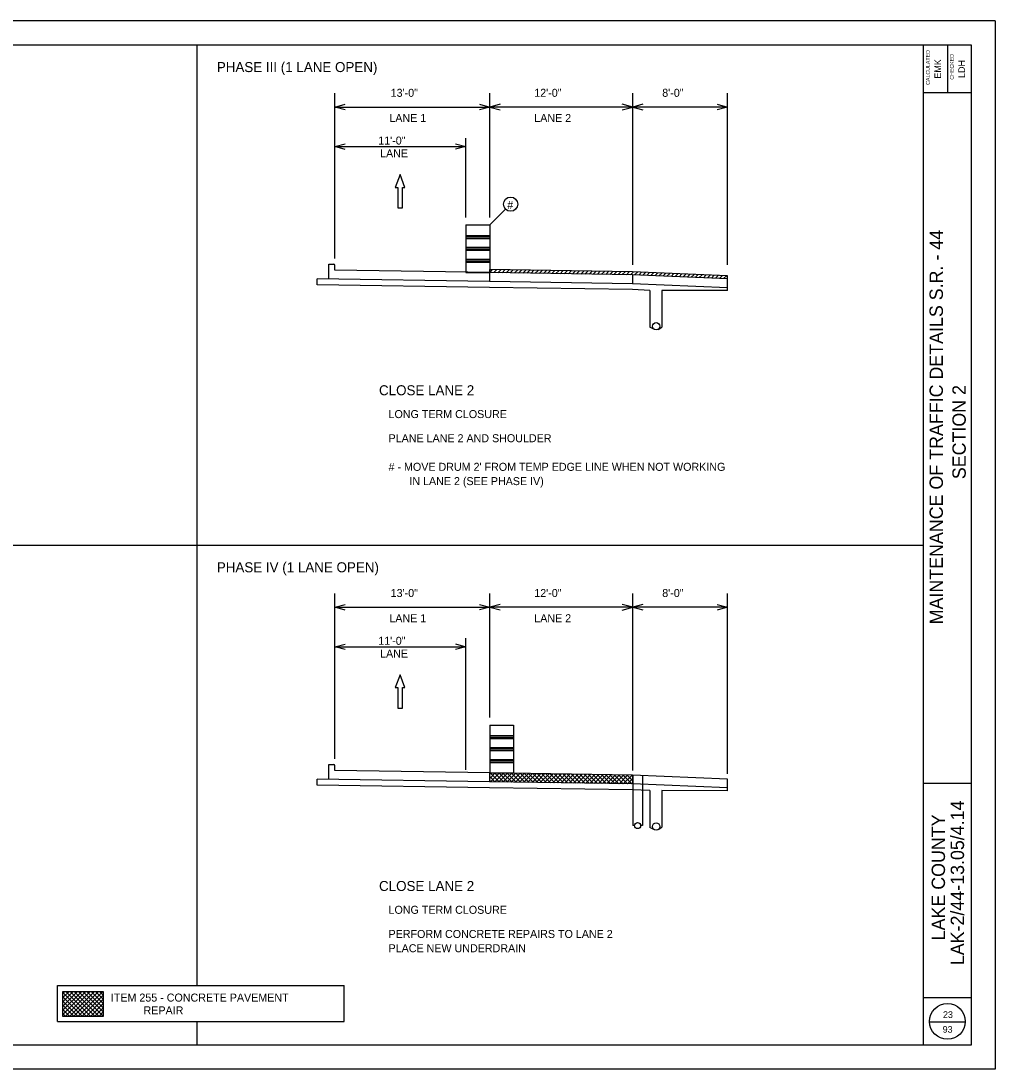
# Model space of a CAD drawing. Extents: x -161 to 291, y -369 to 173.
# Drawn here: x 117.8 to 199.6, y -270.5 to -182.5 of the extents above; entities that cross this region are included whole.
import ezdxf

# ---------------------------------------------------------------- set-up
doc = ezdxf.new("R2010")
doc.units = 0
for name, color, linetype in [('Level 1', 7, 'Continuous'), ('Level 11', 7, 'Continuous'), ('Level 21', 7, 'Continuous'), ('Level 25', 7, 'Continuous'), ('Level 26', 7, 'Continuous'), ('Level 6', 7, 'Continuous'), ('Level 7', 7, 'Continuous')]:
    doc.layers.add(name, color=color, linetype=linetype)

msp = doc.modelspace()

# ---------------------------------------------------------------- linework, layer by layer
at = {"layer": 'Level 1'}
for p, q in [((199.609, -182.503), (63.623, -182.503)), ((199.609, -182.503), (199.609, -270.494)), ((71.623, -184.503), (132.616, -184.503)), ((132.616, -226.499), (132.616, -184.503)), ((132.616, -184.503), (197.61, -184.503)), ((193.61, -201.501), (193.61, -184.503)), ((195.61, -184.503), (195.61, -188.503)), ((197.61, -184.503), (197.61, -268.494)), ((193.61, -188.503), (197.61, -188.503)), ((193.61, -246.497), (193.61, -201.501)), ((71.623, -226.499), (132.616, -226.499)), ((132.616, -263.494), (132.616, -226.499)), ((132.616, -226.499), (193.61, -226.499)), ((193.61, -251.496), (193.61, -246.497)), ((193.61, -246.497), (197.61, -246.497)), ((193.61, -268.494), (193.61, -251.496)), ((120.876, -263.494), (144.954, -263.494)), ((120.876, -266.494), (120.876, -263.494)), ((144.954, -266.494), (144.954, -263.494)), ((120.876, -266.494), (144.954, -266.494)), ((132.616, -268.494), (132.616, -266.494)), ((197.61, -268.494), (71.623, -268.494)), ((199.609, -270.494), (63.623, -270.494))]:
    msp.add_line(p, q, dxfattribs=at)
at = {"layer": 'Level 11'}
for p, q in [((143.682, -204.168), (143.682, -202.928)), ((143.682, -202.928), (144.099, -202.928)), ((144.182, -203.428), (144.182, -203.011)), ((157.182, -203.629), (144.182, -203.428)), ((157.182, -203.629), (157.182, -203.379)), ((157.182, -203.613), (157.413, -203.382)), ((169.158, -203.814), (157.182, -203.629)), ((157.182, -204.377), (157.182, -203.629)), ((169.155, -203.564), (157.186, -203.379)), ((157.515, -203.634), (157.761, -203.388)), ((157.863, -203.639), (158.109, -203.393)), ((158.211, -203.645), (158.457, -203.399)), ((158.559, -203.65), (158.805, -203.404)), ((158.907, -203.656), (159.154, -203.409)), ((159.256, -203.661), (159.502, -203.415)), ((159.604, -203.666), (159.85, -203.42)), ((159.952, -203.672), (160.198, -203.425)), ((160.3, -203.677), (160.546, -203.431)), ((160.648, -203.683), (160.894, -203.436)), ((160.996, -203.688), (161.243, -203.442)), ((161.345, -203.693), (161.591, -203.447)), ((161.693, -203.699), (161.939, -203.452)), ((162.041, -203.704), (162.287, -203.458)), ((162.389, -203.709), (162.635, -203.463)), ((162.737, -203.715), (162.984, -203.469)), ((163.085, -203.72), (163.332, -203.474)), ((163.434, -203.726), (163.68, -203.479)), ((163.782, -203.731), (164.028, -203.485)), ((164.13, -203.736), (164.376, -203.49)), ((164.478, -203.742), (164.724, -203.495)), ((164.826, -203.747), (165.073, -203.501)), ((165.174, -203.752), (165.421, -203.506)), ((165.523, -203.758), (165.769, -203.512)), ((165.871, -203.763), (166.117, -203.517)), ((166.219, -203.769), (166.465, -203.522)), ((166.567, -203.774), (166.813, -203.528)), ((166.915, -203.779), (167.162, -203.533)), ((167.263, -203.785), (167.51, -203.538)), ((167.612, -203.79), (167.858, -203.544)), ((167.96, -203.796), (168.206, -203.549)), ((168.308, -203.801), (168.554, -203.555)), ((168.656, -203.806), (168.902, -203.56)), ((169.004, -203.812), (169.248, -203.568)), ((177.155, -203.899), (169.155, -203.564)), ((177.155, -204.149), (169.158, -203.814)), ((169.182, -204.563), (169.182, -203.814)), ((169.348, -203.822), (169.588, -203.582)), ((169.687, -203.836), (169.927, -203.596)), ((170.026, -203.85), (170.266, -203.61)), ((170.366, -203.865), (170.606, -203.625)), ((170.705, -203.879), (170.945, -203.639)), ((171.044, -203.893), (171.284, -203.653)), ((171.384, -203.907), (171.624, -203.667)), ((171.723, -203.921), (171.963, -203.681)), ((172.062, -203.936), (172.302, -203.696)), ((172.402, -203.95), (172.642, -203.71)), ((172.741, -203.964), (172.981, -203.724)), ((173.08, -203.978), (173.32, -203.738)), ((173.42, -203.993), (173.66, -203.753)), ((173.759, -204.007), (173.999, -203.767)), ((174.098, -204.021), (174.338, -203.781)), ((174.438, -204.035), (174.678, -203.795)), ((174.777, -204.049), (175.017, -203.809)), ((175.116, -204.064), (175.356, -203.824)), ((175.456, -204.078), (175.696, -203.838)), ((175.795, -204.092), (176.035, -203.852)), ((176.134, -204.106), (176.374, -203.866)), ((176.474, -204.12), (176.714, -203.88)), ((176.813, -204.135), (177.053, -203.895)), ((177.155, -205.146), (177.155, -203.899)), ((157.166, -204.377), (142.681, -204.153)), ((157.166, -204.876), (142.681, -204.653)), ((142.682, -204.653), (142.682, -204.153)), ((169.157, -205.062), (157.168, -204.877)), ((169.175, -204.562), (157.182, -204.377)), ((177.152, -204.896), (169.175, -204.562)), ((177.152, -204.149), (177.155, -204.146)), ((170.63, -205.124), (169.157, -205.062)), ((170.633, -205.124), (170.633, -208.215)), ((171.633, -205.127), (171.633, -208.204)), ((177.155, -205.146), (171.633, -205.127)), ((171.02, -208.407), (170.633, -208.215)), ((171.31, -208.396), (171.633, -208.204)), ((143.682, -246.164), (143.682, -244.924)), ((143.682, -244.924), (144.099, -244.924)), ((144.182, -245.424), (144.182, -245.007)), ((157.182, -245.625), (144.182, -245.424)), ((157.166, -246.372), (142.681, -246.149)), ((142.682, -246.648), (142.682, -246.149)), ((169.158, -245.81), (157.182, -245.625)), ((157.182, -246.373), (157.182, -245.625)), ((169.175, -246.558), (157.182, -246.373)), ((177.155, -246.145), (169.158, -245.81)), ((169.182, -246.558), (169.182, -245.81)), ((177.155, -247.142), (177.155, -246.145)), ((157.166, -246.872), (142.681, -246.648)), ((169.157, -247.058), (157.168, -246.872)), ((170.63, -247.119), (169.157, -247.058)), ((177.152, -246.892), (169.175, -246.558)), ((170.633, -247.119), (170.633, -250.211)), ((171.633, -247.123), (171.633, -250.2)), ((177.155, -247.142), (171.633, -247.123)), ((171.02, -250.403), (170.633, -250.211)), ((171.31, -250.392), (171.633, -250.2))]:
    msp.add_line(p, q, dxfattribs=at)
for centre in [(171.155, -208.134), (171.155, -250.13)]:
    msp.add_circle(centre, 0.304, dxfattribs=at)
for centre in [(144.099, -203.011), (144.099, -245.007)]:
    msp.add_arc(centre, 0.083, 0, 90, dxfattribs=at)
at = {"layer": 'Level 21'}
for p, q in [((157.182, -245.736), (157.291, -245.626)), ((157.182, -246.089), (157.639, -245.632)), ((157.182, -245.945), (157.616, -246.379)), ((157.182, -246.299), (157.257, -246.374)), ((157.215, -245.625), (157.975, -246.385)), ((157.251, -246.374), (157.987, -245.637)), ((157.574, -245.631), (158.334, -246.391)), ((157.599, -246.379), (158.335, -245.643)), ((157.933, -245.636), (158.693, -246.396)), ((157.947, -246.385), (158.683, -245.648)), ((158.292, -245.642), (159.052, -246.402)), ((158.295, -246.39), (159.032, -245.653)), ((158.643, -246.395), (159.38, -245.659)), ((158.651, -245.647), (159.411, -246.407)), ((158.991, -246.401), (159.728, -245.664)), ((159.011, -245.653), (159.77, -246.413)), ((159.34, -246.406), (160.076, -245.67)), ((159.37, -245.659), (160.129, -246.418)), ((159.688, -246.411), (160.424, -245.675)), ((159.729, -245.664), (160.489, -246.424)), ((160.036, -246.417), (160.772, -245.68)), ((160.088, -245.67), (160.848, -246.429)), ((160.384, -246.422), (161.121, -245.686)), ((160.447, -245.675), (161.207, -246.435)), ((160.732, -246.428), (161.469, -245.691)), ((160.806, -245.681), (161.566, -246.441)), ((161.08, -246.433), (161.817, -245.696)), ((161.165, -245.686), (161.925, -246.446)), ((161.428, -246.438), (162.165, -245.702)), ((161.524, -245.692), (162.284, -246.452)), ((161.777, -246.444), (162.513, -245.707)), ((161.883, -245.697), (162.643, -246.457)), ((162.125, -246.449), (162.862, -245.713)), ((162.242, -245.703), (163.002, -246.463)), ((162.473, -246.455), (163.21, -245.718)), ((162.602, -245.709), (163.361, -246.468)), ((162.821, -246.46), (163.558, -245.723)), ((162.961, -245.714), (163.721, -246.474)), ((163.169, -246.465), (163.906, -245.729)), ((163.32, -245.72), (164.08, -246.479)), ((163.517, -246.471), (164.254, -245.734)), ((163.679, -245.725), (164.439, -246.485)), ((163.866, -246.476), (164.602, -245.739)), ((164.038, -245.731), (164.798, -246.491)), ((164.214, -246.482), (164.951, -245.745)), ((164.397, -245.736), (165.157, -246.496)), ((164.562, -246.487), (165.299, -245.75)), ((164.756, -245.742), (165.516, -246.502)), ((164.91, -246.492), (165.647, -245.756)), ((165.115, -245.747), (165.875, -246.507)), ((165.258, -246.498), (165.995, -245.761)), ((165.474, -245.753), (166.234, -246.513)), ((165.606, -246.503), (166.343, -245.766)), ((165.833, -245.758), (166.593, -246.518)), ((165.955, -246.509), (166.691, -245.772)), ((166.193, -245.764), (166.953, -246.524)), ((166.303, -246.514), (167.04, -245.777)), ((166.552, -245.77), (167.312, -246.53)), ((166.651, -246.519), (167.388, -245.782)), ((166.911, -245.775), (167.671, -246.535)), ((166.999, -246.525), (167.736, -245.788)), ((167.27, -245.781), (168.03, -246.541)), ((167.347, -246.53), (168.084, -245.793)), ((167.629, -245.786), (168.389, -246.546)), ((167.695, -246.535), (168.432, -245.799)), ((167.988, -245.792), (168.748, -246.552)), ((168.044, -246.541), (168.78, -245.804)), ((168.347, -245.797), (169.107, -246.557)), ((168.392, -246.546), (169.129, -245.809)), ((168.706, -245.803), (169.173, -246.269)), ((168.74, -246.552), (169.168, -246.124)), ((169.065, -245.808), (169.161, -245.904)), ((169.182, -245.81), (169.182, -250.059)), ((170.015, -245.846), (170.015, -250.059)), ((169.088, -246.557), (169.179, -246.466)), ((169.348, -250.059), (169.182, -250.059)), ((170.015, -250.059), (169.848, -250.059)), ((121.338, -264.143), (121.505, -263.976)), ((121.338, -264.497), (121.859, -263.976)), ((121.338, -264.85), (122.213, -263.976)), ((121.338, -265.204), (122.566, -263.976)), ((121.338, -265.557), (122.92, -263.976)), ((121.338, -265.911), (123.273, -263.976)), ((123.335, -266.073), (121.338, -264.077)), ((122.981, -266.073), (121.338, -264.431)), ((122.627, -266.073), (121.338, -264.784)), ((121.53, -266.073), (123.627, -263.976)), ((123.688, -266.073), (121.591, -263.976)), ((121.883, -266.073), (123.98, -263.976)), ((124.042, -266.073), (121.945, -263.976)), ((122.237, -266.073), (124.333, -263.976)), ((124.395, -266.073), (122.298, -263.976)), ((122.59, -266.073), (124.687, -263.976)), ((124.73, -266.054), (122.652, -263.976)), ((122.944, -266.073), (124.73, -264.287)), ((124.73, -265.701), (123.005, -263.976)), ((123.297, -266.073), (124.73, -264.64)), ((124.73, -265.347), (123.359, -263.976)), ((124.73, -264.994), (123.712, -263.976)), ((124.73, -264.64), (124.066, -263.976)), ((124.73, -264.287), (124.42, -263.976)), ((193.61, -264.495), (197.61, -264.495)), ((122.274, -266.073), (121.338, -265.138)), ((121.92, -266.073), (121.338, -265.491)), ((123.651, -266.073), (124.73, -264.994)), ((124.005, -266.073), (124.73, -265.348)), ((124.358, -266.073), (124.73, -265.701)), ((121.567, -266.073), (121.338, -265.845)), ((194.11, -266.522), (197.109, -266.518))]:
    msp.add_line(p, q, dxfattribs=at)
for centre, radius in [((169.598, -250.059), 0.25), ((195.61, -266.495), 1.5)]:
    msp.add_circle(centre, radius, dxfattribs=at)
at = {"layer": 'Level 25'}
for p, q in [((155.182, -199.629), (155.182, -203.629)), ((155.182, -199.629), (157.182, -199.629)), ((157.182, -199.629), (157.182, -203.629)), ((155.182, -200.504), (157.182, -200.504)), ((155.182, -200.629), (157.182, -200.629)), ((155.182, -200.754), (157.182, -200.754)), ((155.182, -201.504), (157.182, -201.504)), ((155.182, -201.629), (157.182, -201.629)), ((155.182, -201.754), (157.182, -201.754)), ((155.182, -202.504), (157.182, -202.504)), ((155.182, -202.629), (157.182, -202.629)), ((155.182, -202.754), (157.182, -202.754)), ((155.182, -203.629), (157.182, -203.629)), ((157.182, -241.625), (157.182, -245.625)), ((157.182, -241.625), (159.182, -241.625)), ((159.182, -241.625), (159.182, -245.625)), ((157.182, -242.5), (159.182, -242.5)), ((157.182, -242.625), (159.182, -242.625)), ((157.182, -242.75), (159.182, -242.75)), ((157.182, -243.5), (159.182, -243.5)), ((157.182, -243.625), (159.182, -243.625)), ((157.182, -243.75), (159.182, -243.75)), ((157.182, -244.5), (159.182, -244.5)), ((157.182, -244.625), (159.182, -244.625)), ((157.182, -244.75), (159.182, -244.75)), ((157.182, -245.625), (159.182, -245.625))]:
    msp.add_line(p, q, dxfattribs=at)
at = {"layer": 'Level 26'}
for p, q in [((144.182, -202.451), (144.182, -188.569)), ((157.182, -198.991), (157.182, -188.569)), ((169.182, -202.982), (169.182, -188.569)), ((177.155, -202.981), (177.155, -188.569)), ((144.182, -189.728), (157.182, -189.728)), ((169.182, -189.728), (157.182, -189.728)), ((177.155, -189.728), (169.182, -189.728)), ((155.182, -198.991), (155.182, -192.338)), ((144.182, -193.049), (155.182, -193.049)), ((157.182, -199.629), (158.511, -198.304)), ((144.182, -244.447), (144.182, -230.565)), ((157.182, -240.986), (157.182, -230.565)), ((169.182, -245.43), (169.182, -230.565)), ((177.155, -245.722), (177.155, -230.565)), ((144.182, -231.724), (157.182, -231.724)), ((169.182, -231.724), (157.182, -231.724)), ((177.155, -231.724), (169.182, -231.724)), ((155.182, -245.378), (155.182, -234.333)), ((144.182, -235.045), (155.182, -235.045))]:
    msp.add_line(p, q, dxfattribs=at)
for points in [[(145.048, -189.968), (144.182, -189.728), (145.048, -189.497)], [(156.316, -189.489), (157.182, -189.728), (156.316, -189.959)], [(158.048, -189.489), (157.182, -189.728), (158.048, -189.959)], [(168.313, -189.968), (169.182, -189.728), (168.313, -189.497)], [(170.048, -189.489), (169.182, -189.728), (170.048, -189.959)], [(176.287, -189.489), (177.155, -189.728), (176.287, -189.96)], [(145.048, -193.288), (144.182, -193.049), (145.048, -192.818)], [(154.316, -192.81), (155.182, -193.049), (154.316, -193.28)], [(145.048, -231.963), (144.182, -231.724), (145.048, -231.493)], [(156.316, -231.485), (157.182, -231.724), (156.316, -231.955)], [(158.048, -231.485), (157.182, -231.724), (158.048, -231.955)], [(168.313, -231.964), (169.182, -231.724), (168.313, -231.493)], [(170.048, -231.485), (169.182, -231.724), (170.048, -231.955)], [(176.287, -231.484), (177.155, -231.724), (176.287, -231.956)], [(145.048, -235.284), (144.182, -235.045), (145.048, -234.814)], [(154.316, -234.805), (155.182, -235.045), (154.316, -235.276)]]:
    msp.add_lwpolyline(points, dxfattribs=at)
msp.add_circle((158.934, -197.882), 0.597, dxfattribs=at)
at = {"layer": 'Level 6'}
msp.add_lwpolyline([(121.338, -263.976), (124.73, -263.976), (124.73, -266.073), (121.338, -266.073)], close=True, dxfattribs=at)
at = {"layer": 'Level 7'}
for p, q in [((149.648, -195.407), (149.251, -196.477)), ((150.051, -196.477), (149.648, -195.407)), ((149.251, -196.477), (149.456, -196.477)), ((149.456, -196.477), (149.456, -198.205)), ((149.846, -198.205), (149.846, -196.477)), ((149.846, -196.477), (150.051, -196.477)), ((149.456, -198.205), (149.846, -198.205)), ((149.648, -237.402), (149.251, -238.473)), ((150.051, -238.473), (149.648, -237.402)), ((149.251, -238.473), (149.456, -238.473)), ((149.456, -238.473), (149.456, -240.2)), ((149.846, -240.2), (149.846, -238.473)), ((149.846, -238.473), (150.051, -238.473)), ((149.456, -240.2), (149.846, -240.2))]:
    msp.add_line(p, q, dxfattribs=at)

# ---------------------------------------------------------------- texts
at = {"layer": 'Level 1'}
for s, height, p in [('CALCULATED', 0.32, (194.127, -187.867)), ('CHECKED', 0.32, (196.149, -187.434)), ('EMK', 0.5599, (195.085, -187.34)), ('LDH', 0.5599, (197.085, -187.287)), ('MAINTENANCE OF TRAFFIC DETAILS S.R. - 44', 1.11989, (195.231, -233.159)), ('SECTION 2', 1.1199, (197.151, -220.974)), ('LAK-2/44-13.05/4.14', 1.11989, (197.007, -261.773)), ('LAKE COUNTY', 1.11989, (195.408, -259.688))]:
    msp.add_text(s, height=height, rotation=90, dxfattribs=at).set_placement(p)
for s, p in [('23', (195.238, -266.203)), ('93', (195.213, -267.446))]:
    msp.add_text(s, height=0.5599, dxfattribs=at).set_placement(p)
at = {"layer": 'Level 26'}
for s, p in [('13\'-0"', (148.863, -188.871)), ('12\'-0"', (160.92, -188.871)), ('8\'-0"', (171.665, -188.871)), ('LANE 1', (148.752, -190.987)), ('LANE 2', (160.92, -190.987)), ('11\'-0"', (147.819, -192.881)), ('LANE', (147.974, -193.953)), ('#', (158.65, -198.284)), ('13\'-0"', (148.863, -230.867)), ('12\'-0"', (160.92, -230.867)), ('8\'-0"', (171.665, -230.867)), ('LANE 1', (148.752, -232.983)), ('LANE 2', (160.92, -232.983)), ('11\'-0"', (147.819, -234.877)), ('LANE', (147.974, -235.949))]:
    msp.add_text(s, height=0.672, dxfattribs=at).set_placement(p)
at = {"layer": 'Level 6'}
for s, height, p in [('PHASE III (1 LANE OPEN)', 0.84, (134.266, -186.794)), ('CLOSE LANE 2', 0.84, (147.884, -213.927)), ('LONG TERM CLOSURE', 0.672, (148.684, -215.843)), ('PLANE LANE 2 AND SHOULDER', 0.672, (148.684, -217.871)), ("# - MOVE DRUM 2' FROM TEMP EDGE LINE WHEN NOT WORKING", 0.672, (148.684, -220.271)), ('       IN LANE 2 (SEE PHASE IV)', 0.672, (148.684, -221.471)), ('PHASE IV (1 LANE OPEN)', 0.84, (134.266, -228.79)), ('CLOSE LANE 2', 0.84, (147.884, -255.546)), ('LONG TERM CLOSURE', 0.672, (148.684, -257.462)), ('PERFORM CONCRETE REPAIRS TO LANE 2', 0.672, (148.684, -259.49)), ('PLACE NEW UNDERDRAIN ', 0.672, (148.684, -260.689)), ('ITEM 255 - CONCRETE PAVEMENT', 0.672, (125.366, -264.831)), ('           REPAIR', 0.672, (125.366, -265.903))]:
    msp.add_text(s, height=height, dxfattribs=at).set_placement(p)

doc.saveas('drawing.dxf')
